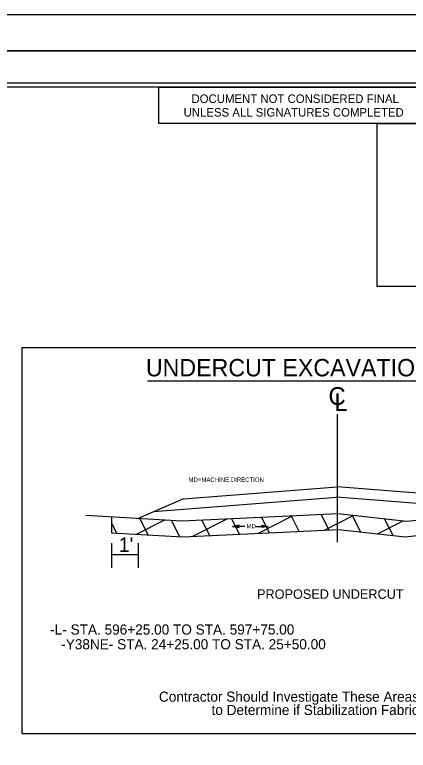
# Model space of a CAD drawing. Extents: x 2294342 to 2294901, y 719427 to 719941.
# Drawn here: x 2294685.4 to 2294739.6, y 719839.8 to 719941.1 of the extents above; entities that cross this region are included whole.
import ezdxf

# ---------------------------------------------------------------- set-up
doc = ezdxf.new("R2010")
doc.units = 0
for name, color, linetype in [('Default', 7, 'Continuous'), ('Old_Level_11', 7, 'Continuous'), ('Old_Level_3', 7, 'Continuous'), ('Prop Dimension', 7, 'Continuous'), ('Prop Terminator CELL', 7, 'Continuous'), ('Prop XS Undercut Exc', 7, 'Continuous'), ('Raster_Level_2', 7, 'Continuous'), ('Sheet Plan CELL', 7, 'Continuous'), ('Sheet Plot Border Inside CELL', 7, 'Continuous'), ('Sheet Plot Border Outside CELL', 7, 'Continuous'), ('Sheet Sticker Exception Certification CELL', 7, 'Continuous'), ('Sheet Typical CELL', 7, 'Continuous'), ('Typical Detail Wedge2 CELL', 7, 'Continuous'), ('Typical Hinge Slope Interstate CELL', 7, 'Continuous'), ('Typical Pavement Slope CELL', 7, 'Continuous'), ('Typical Text Centerline CELL', 7, 'Continuous'), ('Typical Text General CELL', 7, 'Continuous')]:
    doc.layers.add(name, color=color, linetype=linetype)

msp = doc.modelspace()

# ---------------------------------------------------------------- linework, layer by layer
at = {"layer": 'Default'}
msp.add_line((2294454.52, 719936.17), (2294794.52, 719936.17), dxfattribs=at)
msp.add_lwpolyline([(2294454.52, 719936.17), (2294794.52, 719936.17), (2294794.52, 719716.17), (2294454.52, 719716.17)], close=True, dxfattribs=at)
msp.add_lwpolyline([(2294454.52, 719936.17), (2294794.52, 719936.17), (2294794.52, 719716.17), (2294454.52, 719716.17)], close=True, dxfattribs=at)
at = {"layer": 'Old_Level_11'}
for p, q in [((2294729.86, 719886.1), (2294729.85, 719868.43)), ((2294698.78, 719868.32), (2294698.78, 719864.9)), ((2294702.46, 719868.32), (2294702.46, 719864.9)), ((2294698.83, 719866.75), (2294702.46, 719866.75))]:
    msp.add_line(p, q, dxfattribs=at)
at = {"layer": 'Prop Dimension'}
for p, q in [((2294717.15, 719870.62), (2294715.44, 719870.62)), ((2294718.65, 719870.62), (2294720.35, 719870.62))]:
    msp.add_line(p, q, dxfattribs=at)
at = {"layer": 'Prop Terminator CELL'}
for points in [[(2294716.34, 719870.77), (2294715.44, 719870.62), (2294716.34, 719870.46), (2294716.23, 719870.62)], [(2294719.45, 719870.77), (2294720.35, 719870.62), (2294719.45, 719870.46), (2294719.56, 719870.62)]]:
    msp.add_lwpolyline(points, close=True, dxfattribs=at)
at = {"layer": 'Prop XS Undercut Exc'}
for p, q in [((2294698.78, 719871.95), (2294698.78, 719869.74)), ((2294702.23, 719869.53), (2294706.1, 719871.51)), ((2294703.84, 719869.44), (2294702.68, 719871.71)), ((2294708.18, 719869.18), (2294707.02, 719871.45)), ((2294709.89, 719869.23), (2294714.69, 719871.68)), ((2294712.31, 719869.35), (2294711.21, 719871.5)), ((2294716.41, 719869.55), (2294715.31, 719871.71)), ((2294719.03, 719869.68), (2294723.8, 719872.11)), ((2294720.52, 719869.75), (2294719.42, 719871.91)), ((2294724.63, 719869.93), (2294723.53, 719872.1)), ((2294728.75, 719870.12), (2294727.65, 719872.28)), ((2294728.1, 719870.09), (2294732.13, 719872.15)), ((2294733.1, 719869.84), (2294731.91, 719872.17)), ((2294737.56, 719869.36), (2294736.37, 719871.68)), ((2294699.5, 719869.69), (2294698.78, 719871.1)), ((2294735.38, 719869.59), (2294738.93, 719871.4)), ((2294698.78, 719869.74), (2294708.56, 719869.16)), ((2294708.56, 719869.16), (2294719.49, 719869.7)), ((2294719.49, 719869.7), (2294730.03, 719870.18)), ((2294730.03, 719870.18), (2294739.2, 719869.18)), ((2294739.2, 719869.18), (2294746.3, 719869.95))]:
    msp.add_line(p, q, dxfattribs=at)
at = {"layer": 'Raster_Level_2'}
msp.add_line((2294703.74, 719890.67), (2294755.76, 719890.67), dxfattribs=at)
at = {"layer": 'Sheet Plan CELL'}
msp.add_lwpolyline([(2294761.64, 719903.66), (2294735.35, 719903.66), (2294735.35, 719926.16), (2294761.64, 719926.16)], dxfattribs=at)
at = {"layer": 'Sheet Plot Border Inside CELL'}
msp.add_lwpolyline([(2294790.42, 719931.68), (2294457.12, 719931.68), (2294457.12, 719720.66), (2294790.42, 719720.66)], close=True, dxfattribs=at)
at = {"layer": 'Sheet Plot Border Outside CELL'}
for points in [[(2294793.79, 719941.13), (2294456.99, 719941.13), (2294456.99, 719721.13), (2294793.79, 719721.13)], [(2294794.52, 719936.17), (2294454.52, 719936.17), (2294454.52, 719716.17), (2294794.52, 719716.17)]]:
    msp.add_lwpolyline(points, close=True, dxfattribs=at)
at = {"layer": 'Sheet Sticker Exception Certification CELL'}
for p, q in [((2294705.29, 719926.16), (2294705.29, 719931.17)), ((2294705.29, 719931.17), (2294747.91, 719931.17)), ((2294747.91, 719926.16), (2294705.29, 719926.16))]:
    msp.add_line(p, q, dxfattribs=at)
at = {"layer": 'Sheet Typical CELL'}
msp.add_lwpolyline([(2294787.92, 719931.17), (2294487.92, 719931.17), (2294487.92, 719721.17), (2294787.92, 719721.17)], close=True, dxfattribs=at)
at = {"layer": 'Typical Detail Wedge2 CELL'}
msp.add_line((2294686.49, 719842.09), (2294686.49, 719895.28), dxfattribs=at)
at = {"layer": 'Typical Pavement Slope CELL'}
for p, q in [((2294708.67, 719874.41), (2294729.86, 719876.09)), ((2294751.04, 719874.41), (2294729.86, 719876.09)), ((2294704.61, 719872.66), (2294729.74, 719874.65)), ((2294757.68, 719872.43), (2294729.74, 719874.65)), ((2294708.67, 719874.41), (2294702.46, 719871.72)), ((2294695.24, 719872.15), (2294708.45, 719871.37)), ((2294708.45, 719871.37), (2294719.38, 719871.91)), ((2294719.38, 719871.91), (2294729.93, 719872.39)), ((2294729.93, 719872.39), (2294739.44, 719871.35)), ((2294739.44, 719871.35), (2294746.07, 719872.07))]:
    msp.add_line(p, q, dxfattribs=at)
at = {"layer": 'Typical Text General CELL'}
for p, q in [((2294686.49, 719895.28), (2294786.23, 719895.28)), ((2294686.49, 719842.09), (2294786.23, 719842.09))]:
    msp.add_line(p, q, dxfattribs=at)

# ---------------------------------------------------------------- texts
at = {"layer": 'Old_Level_3'}
msp.add_text('PROPOSED UNDERCUT', height=1.3056, dxfattribs=at).set_placement((2294718.81, 719860.64))
at = {"layer": 'Raster_Level_2'}
msp.add_text(' UNDERCUT EXCAVATION DETAIL', height=2.3871, rotation=360, dxfattribs=at).set_placement((2294702.62, 719891.3))
msp.add_text('-L- STA. 596+25.00 TO STA. 597+75.00', height=1.4, dxfattribs=at).set_placement((2294690.33, 719855.71))
at = {"layer": 'Sheet Sticker Exception Certification CELL'}
for s, p in [('DOCUMENT NOT CONSIDERED FINAL', (2294709.78, 719928.97)), ('UNLESS ALL SIGNATURES COMPLETED', (2294708.7, 719927.09))]:
    msp.add_text(s, height=1.1719, dxfattribs=at).set_placement(p)
at = {"layer": 'Typical Hinge Slope Interstate CELL'}
for s, p in [('MD=MACHINE DIRECTION', (2294709.37, 719876.76)), ('MD', (2294717.36, 719870.37))]:
    msp.add_text(s, height=0.6, dxfattribs=at).set_placement(p)
at = {"layer": 'Typical Pavement Slope CELL'}
for s, height, p in [("1'", 2.008, (2294699.77, 719867.09)), ('-Y38NE- STA. 24+25.00 TO STA. 25+50.00', 1.4, (2294691.85, 719853.68)), ('Contractor Should Investigate These Areas During Construction', 1.4, (2294705.31, 719846.46)), ('to Determine if Stabilization Fabric is Required', 1.4, (2294712.55, 719844.63))]:
    msp.add_text(s, height=height, dxfattribs=at).set_placement(p)
at = {"layer": 'Typical Text Centerline CELL'}
for s, rotation, p in [('C', 0.0443, (2294728.64, 719887.35)), ('L', 359.9912, (2294729.45, 719886.52))]:
    msp.add_text(s, height=2.46, rotation=rotation, dxfattribs=at).set_placement(p)

doc.saveas('drawing.dxf')
